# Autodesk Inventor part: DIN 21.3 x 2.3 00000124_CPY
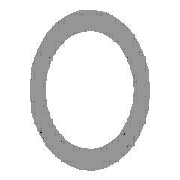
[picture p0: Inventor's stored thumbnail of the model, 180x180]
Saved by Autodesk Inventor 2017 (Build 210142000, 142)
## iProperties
Created: 2017-11
Part Number: DIN 21.3 x 2.3 00000124_CPY
Material: Steel, Mild
Description: Pipe
Document SubType Name: Modeling
Standard: DIN
Designer: iusti
Standard Revision: 2006-07
Standards Organization: DIN
Language: en-US
Size Designation: 21.3 x 2.3
Categories: <MemberInstance><Categories><Category DisplayName="Structural Shapes" InternalName="089c4875-fa83-4c05-b084-43b9cc11f5ed" Mnemonic="GRDR"><CategoryParameter Dis
Stock Number: 21.3 x 2.3
Density: 7.85 g/cm^3
Appearance: Semi-Polished
_CCFamilyMember: 1
_CCFamilyDisplayName: DIN EN 10210-2 - Pipe
_FrameMemberDoc: Frame Member File
_Version: 15.0.0
_GetPNFromCC: 1
IsCustomPart: 1
Author: iusti
G_L: 500.000 mm
G_W: 21.300 mm
G_H: 21.300 mm
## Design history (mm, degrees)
node "Start plane"
node "End plane"
sketch "Sketch"
  geometry: C1 r 8.35 at (0, 0); C2 r 10.65 at (0, 0); 2 further points
  constraints: 3 coincident, 2 centre point
  dimensions: "d0" = 21.3 diameter of C2 (= G_H); "d1" = 2.3 radial gap between concentric circles of C2 C1 (= G_T)
extrude "Body" new body sketch "Sketch" stored distance "d2" = 500 (= G_L); taper "d3" = 0 deg
node "Driven Length"
  sketch "Sketch3"
    geometry: L1 (0, 0)-(10, 0) reference
    constraints: 2 end point, 1 horizontal
  workplane "Work Plane3"
  sketch "Sketch4"
    geometry: L1 (-2, 0)-(12, 0) reference; L2 (-2, 500)-(12, 500) reference
    dimensions: "d7" = 500 distance between parallel lines of L1 L2 (derived)
body "Solid1"
other parameters: "G_H" = 21.3 [user parameter; used in 1 equation term], "G_T" = 2.3 [user parameter; used in 1 equation term], "G_L" = 500 (= d7) [user parameter; used in 1 equation term], "G_OFFSET_START" = 0 [user parameter; used in 1 equation term], "G_OFFSET_END" = 0 [user parameter; used in 1 equation term], "d4" = 0 (computed from G_OFFSET_START), "d6" = 90 deg
